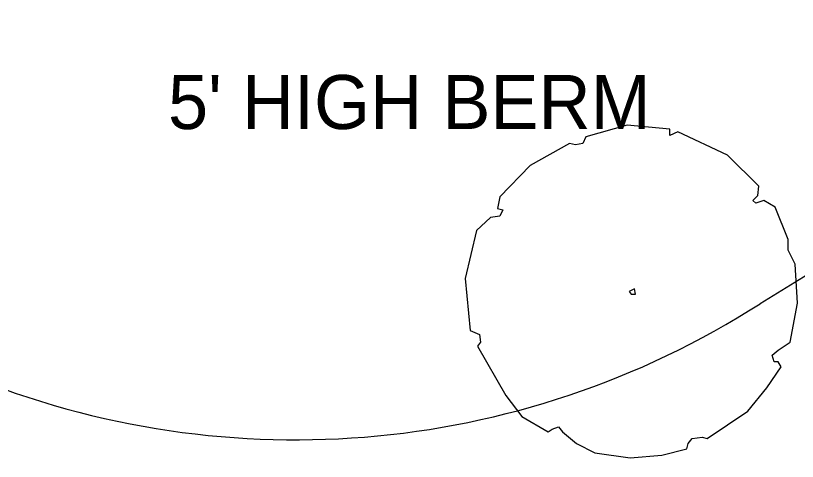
# Model space of a CAD drawing. Extents: x 6712138 to 6712574, y 1869536 to 1870160.
# Drawn here: x 6712243.9 to 6712296.1, y 1869567 to 1869596.7 of the extents above; entities that cross this region are included whole.
import ezdxf

# ---------------------------------------------------------------- set-up
doc = ezdxf.new("R2010")
doc.units = 0
for name, color, linetype in [('A-COLS', 7, 'Continuous'), ('A-WALL', 7, 'Continuous'), ('C-Boun', 7, 'Continuous'), ('L-tree', 7, 'Continuous')]:
    doc.layers.add(name, color=color, linetype=linetype)

# ---------------------------------------------------------------- blocks, each defined once
blk = doc.blocks.new('TREE 1')
at = {"layer": 'L-tree'}
for p, q in [((-0.0275, 0.572), (-0.1682, 0.5324)), ((0.1167, 0.5588), (-0.0275, 0.572)), ((0.1167, 0.5368), (0.1167, 0.5588)), ((-0.1682, 0.5324), (-0.1785, 0.5104)), ((0.1441, 0.55), (0.1167, 0.5368)), ((0.3123, 0.4708), (0.1441, 0.55)), ((-0.2231, 0.5104), (-0.357, 0.4356)), ((-0.2025, 0.506), (-0.2231, 0.5104)), ((-0.1785, 0.5104), (-0.2025, 0.506)), ((0.4187, 0.3652), (0.3123, 0.4708)), ((-0.357, 0.4356), (-0.4599, 0.33)), ((0.4153, 0.3344), (0.4187, 0.3652)), ((-0.4599, 0.33), (-0.4668, 0.2904)), ((0.3981, 0.3168), (0.4153, 0.3344)), ((0.4084, 0.308), (0.3981, 0.3168)), ((0.4359, 0.3168), (0.4084, 0.308)), ((0.4737, 0.2948), (0.4359, 0.3168)), ((0.5183, 0.1848), (0.4737, 0.2948)), ((-0.4668, 0.2904), (-0.4496, 0.286)), ((-0.4496, 0.286), (-0.4599, 0.264)), ((-0.4908, 0.2596), (-0.5389, 0.2156)), ((-0.4599, 0.264), (-0.4908, 0.2596)), ((-0.5389, 0.2156), (-0.5766, 0.0528)), ((0.5183, 0.1496), (0.5183, 0.1848)), ((0.5423, 0.1012), (0.5183, 0.1496)), ((0.5492, -0.0308), (0.5423, 0.1012)), ((-0.5766, 0.0528), (-0.5595, -0.1232)), ((-0.0034, 0.0176), (-0.0206, 0.0088)), ((-0.0206, 0.0088), (-0.0137, 0)), ((-0.0137, 0), (0, 0)), ((0, 0), (-0.0034, 0.0176)), ((0.5251, -0.1628), (0.5492, -0.0308)), ((-0.5595, -0.1232), (-0.5286, -0.1364)), ((-0.5286, -0.1364), (-0.5251, -0.1628)), ((-0.5251, -0.1628), (-0.5354, -0.176)), ((-0.5354, -0.176), (-0.4393, -0.3432)), ((0.4839, -0.1892), (0.5251, -0.1628)), ((0.4634, -0.2068), (0.4839, -0.1892)), ((0.4702, -0.2288), (0.4634, -0.2068)), ((0.4839, -0.2288), (0.4702, -0.2288)), ((0.4942, -0.2464), (0.4839, -0.2288)), ((0.4462, -0.3168), (0.4942, -0.2464)), ((0.381, -0.396), (0.4462, -0.3168)), ((-0.4393, -0.3432), (-0.3844, -0.4136)), ((0.2437, -0.4884), (0.381, -0.396)), ((-0.3844, -0.4136), (-0.2952, -0.4664)), ((-0.2815, -0.4576), (-0.2609, -0.4488)), ((-0.2609, -0.4488), (-0.2471, -0.4664)), ((-0.2952, -0.4664), (-0.2815, -0.4576)), ((-0.2471, -0.4664), (-0.1991, -0.506)), ((0.1785, -0.506), (0.1922, -0.4884)), ((0.1922, -0.4884), (0.2265, -0.484)), ((0.2265, -0.484), (0.2437, -0.4884)), ((-0.1991, -0.506), (-0.1373, -0.5368)), ((0.0892, -0.5456), (0.175, -0.5236)), ((0.175, -0.5236), (0.1785, -0.506)), ((-0.1373, -0.5368), (-0.0172, -0.5544)), ((-0.0172, -0.5544), (0.0892, -0.5456))]:
    blk.add_line(p, q, dxfattribs=at)

msp = doc.modelspace()

# ---------------------------------------------------------------- linework, layer by layer
at = {"layer": 'A-WALL'}
for centre, radius, start, end in [((6712262.565, 1869625.967), 57.555, 190.61512, 302.60212), ((6712382.939, 1869434.436), 168.664, 92.54081, 121.99401)]:
    msp.add_arc(centre, radius, start, end, dxfattribs=at)
at = {"layer": 'C-Boun'}
msp.add_arc((6712717.456, 1868289.472), 1343, 96.709019, 110.149208, dxfattribs=at)

# ---------------------------------------------------------------- block references
at = {"layer": 'L-tree', "xscale": 19.685038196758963, "yscale": 19.685039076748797}
msp.add_blockref('TREE 1', (6712285.256, 1869578.119), dxfattribs=at)

# ---------------------------------------------------------------- texts
at = {"layer": 'A-COLS'}
msp.add_text("5' HIGH BERM", height=3.6, dxfattribs=at).set_placement((6712254.067, 1869589.126))

doc.saveas('drawing.dxf')
